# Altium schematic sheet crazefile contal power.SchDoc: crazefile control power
size A4; CompanyName: 良工作室; DrawnBy: 郑良杰; Engineer: 郑良杰; Organization: 良工作室; DocumentNumber: 4; SheetNumber: 4; SheetTotal: 4
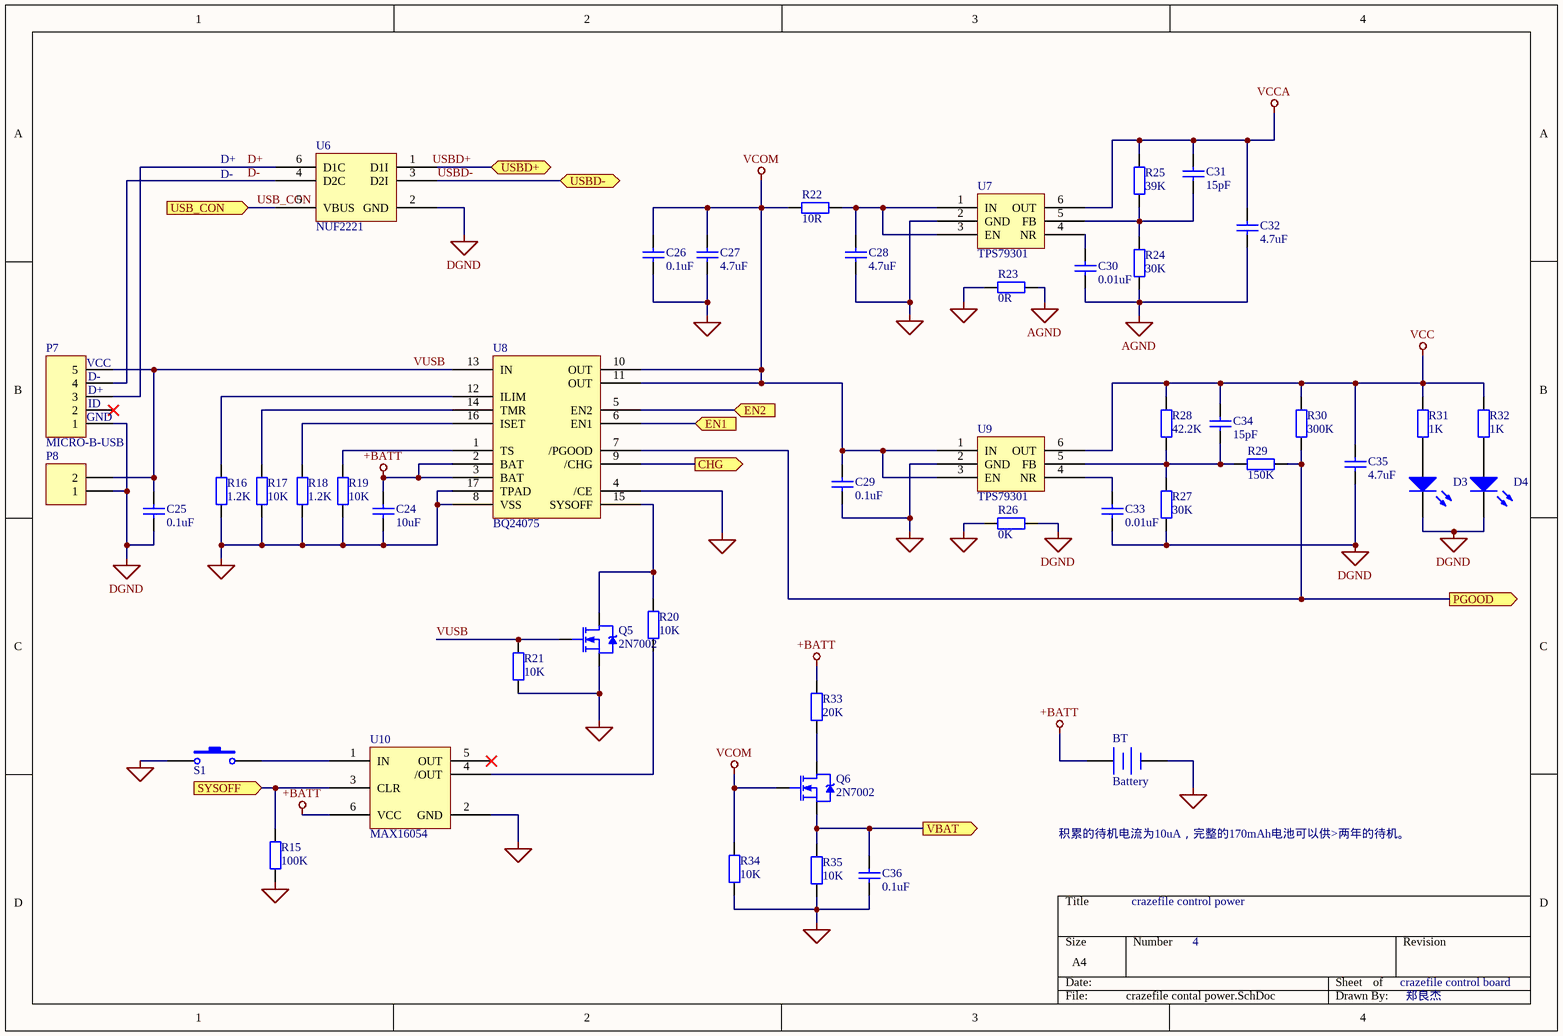
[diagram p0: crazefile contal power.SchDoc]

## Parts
BT  Battery  [BATTERY]
C24  value 10uF  [CAP_0603]  (hidden comment: Cap)
C25  value 0.1uF  [CAP_0603]  (hidden comment: Cap)
C26  value 0.1uF  [CAP_0603]  (hidden comment: Cap)
C27  value 4.7uF  [CAP_0603]  (hidden comment: Cap)
C28  value 4.7uF  [CAP_0603]  (hidden comment: Cap)
C29  value 0.1uF  [CAP_0603]  (hidden comment: Cap)
C30  value 0.01uF  [CAP_0603]  (hidden comment: Cap)
C31  value 15pF  [CAP_0603]  (hidden comment: Cap)
C32  value 4.7uF  [CAP_0603]  (hidden comment: Cap)
C33  value 0.01uF  [CAP_0603]  (hidden comment: Cap)
C34  value 15pF  [CAP_0603]  (hidden comment: Cap)
C35  value 4.7uF  [CAP_0603]  (hidden comment: Cap)
C36  value 0.1uF  [CAP_0603]  (hidden comment: Cap)
D3  LED0  [LED_0603_GREEN]  (value not drawn)
D4  LED0  [LED_0603_RED]  (value not drawn)
P7  MICRO-B-USB  [USB_MICRO_B]
P8  Header 2  [HDR1X2_180_2.54]  (value not drawn)
Q5  2N7002  [SI2302]
Q6  2N7002  [SI2302]
R15  value 100K  [RES_0603]  (hidden comment: Res2)
R16  value 1.2K  [RES_0603]  (hidden comment: Res2)
R17  value 10K  [RES_0603]  (hidden comment: Res2)
R18  value 1.2K  [RES_0603]  (hidden comment: Res2)
R19  value 10K  [RES_0603]  (hidden comment: Res2)
R20  value 10K  [RES_0603]  (hidden comment: Res2)
R21  value 10K  [RES_0603]  (hidden comment: Res2)
R22  value 10R  [RES_0603]  (hidden comment: Res2)
R23  value 0R  [RES_0603]  (hidden comment: Res2)
R24  value 30K  [RES_0603]  (hidden comment: Res2)
R25  value 39K  [RES_0603]  (hidden comment: Res2)
R26  value 0K  [RES_0603]  (hidden comment: Res2)
R27  value 30K  [RES_0603]  (hidden comment: Res2)
R28  value 42.2K  [RES_0603]  (hidden comment: Res2)
R29  value 150K  [RES_0603]  (hidden comment: Res2)
R30  value 300K  [RES_0603]  (hidden comment: Res2)
R31  value 1K  [RES_0603]  (hidden comment: Res2)
R32  value 1K  [RES_0603]  (hidden comment: Res2)
R33  value 20K  [RES_0603]  (hidden comment: Res2)
R34  value 10K  [RES_0603]  (hidden comment: Res2)
R35  value 10K  [RES_0603]  (hidden comment: Res2)
S1  SW-PB  [SKREHE010]  (value not drawn)
U6  NUF2221  [SOT363]
U7  TPS79301  [DBV6]
U8  BQ24075  [QFN17]
U9  TPS79301  [DBV6]
U10  MAX16054  [SOT23-6]

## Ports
CHG (out), EN1 (in), EN2 (in), PGOOD (out), SYSOFF (in), USB_CON (in), USBD+, USBD-, VBAT (out)

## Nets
+BATT: BT.1(+) C24.2 R33.2 U8.2(BAT) U8.3(BAT) U10.6(VCC)
AGND: C30.1 C32.1 R23.1 R24.1
DGND: C25.2 C33.1 C35.2 D3.2(K) D4.2(K) P7.1 P8.1 R26.2 R27.1 U6.2(GND)
GND: BT.2(-) C24.1 C26.1 C27.1 C28.1 C29.1 C36.1 Q5.2(S) R15.1 R16.1 R17.1 R18.1 R19.1 R21.1 R23.2 R26.1 R34.1 R35.1 S1.1 U7.2(GND) U8.4(/CE) U8.8(VSS) U8.17(TPAD) U9.2(GND) U10.2(GND)
VCC: C34.2 C35.1 R28.2 R30.2 R31.2 R32.2 U9.6(OUT)
VCCA: C31.2 C32.2 R25.2 U7.6(OUT)
VCOM: C26.2 C27.2 C29.2 Q6.1(G) R22.2 R34.2 U8.10(OUT) U8.11(OUT) U9.1(IN) U9.3(EN)
CHG: U8.9(/CHG) ; port CHG
D+: P7.3 U6.6(D1C)
D-: P7.4 U6.4(D2C)
EN1: U8.6(EN1) ; port EN1
EN2: U8.5(EN2) ; port EN2
PGOOD: R29.2 R30.1 U8.7(/PGOOD) ; port PGOOD
SYSOFF: R15.2 U10.3(CLR) ; port SYSOFF
USB_CON: U6.5(VBUS) ; port USB_CON
USBD+: U6.1(D1I) ; port USBD+
USBD-: U6.3(D2I) ; port USBD-
VBAT: C36.2 Q6.2(S) R35.2 ; port VBAT
VUSB: C25.1 P7.5 P8.2 Q5.1(G) R21.2 U8.13(IN)
NetC28_2: C28.2 R22.1 U7.1(IN) U7.3(EN)
NetC30_2: C30.2 U7.4(NR)
NetC31_1: C31.1 R24.2 R25.1 U7.5(FB)
NetC33_2: C33.2 U9.4(NR)
NetC34_1: C34.1 R27.2 R28.1 R29.1 U9.5(FB)
NetD3_1: D3.1(A) R31.1
NetD4_1: D4.1(A) R32.1
NetQ5_3: Q5.3(D) R20.2 U8.15(SYSOFF)
NetQ6_3: Q6.3(D) R33.1
NetR16_2: R16.2 U8.12(ILIM)
NetR17_2: R17.2 U8.14(TMR)
NetR18_2: R18.2 U8.16(ISET)
NetR19_2: R19.2 U8.1(TS)
NetR20_1: R20.1 U10.4(/OUT)
NetS1_2: S1.2 U10.1(IN)

Not connected (* = marked no-connect by the designer): P7 2*; U10 5(OUT)*

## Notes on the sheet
- D+
- D-
- (near P7) VCC
- (near P7) D-
- (near P7) GND
- (near P7) D+
- (near P7) ID
- 积累的待机电流为10uA，完整的170mAh电池可以供>两年的待机。
- Labels drawn without touching a wire or pin: USBD+

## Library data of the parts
BT = Battery: Multicell Battery
C24-C36 = Cap: Capacitor
D3 D4 = LED0: Typical INFRARED GaAs LED
P7 = MHDR1X5: Header, 5-Pin
P8 = Header 2: Header, 2-Pin
Q5 Q6 = SI2302_1
R15-R35 = Res2: Resistor
S1 = SW-PB: Switch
